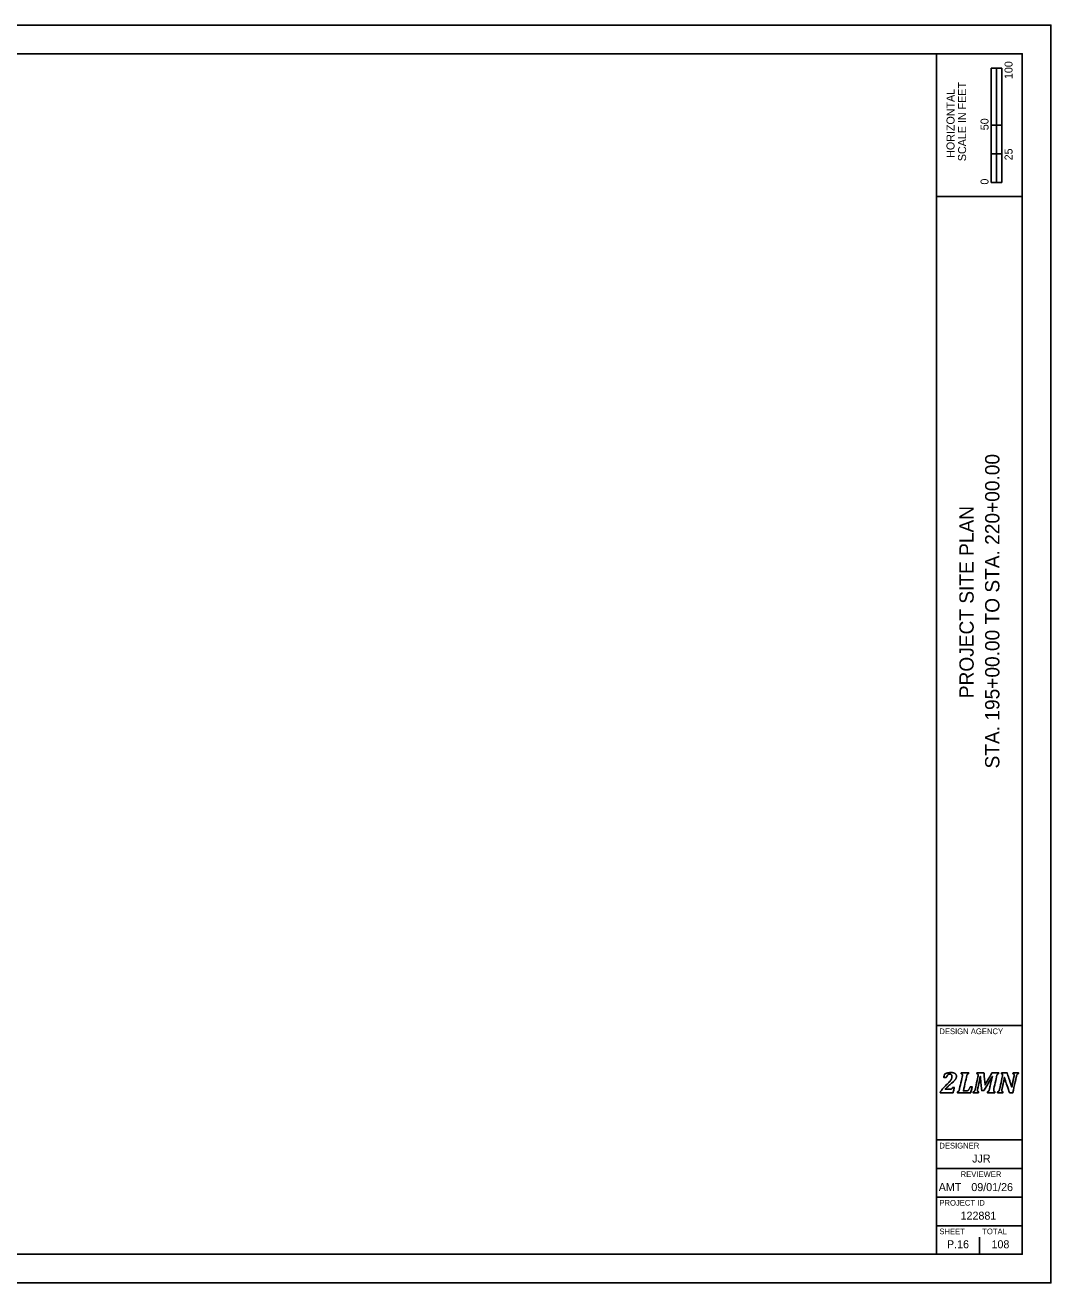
# Model space of a CAD drawing. Extents: x -1.9 to 34, y 0 to 22.
# Drawn here: x 16.06 to 34, y 0 to 22 of the extents above; entities that cross this region are included whole.
import ezdxf

# ---------------------------------------------------------------- set-up
doc = ezdxf.new("R2010")
doc.units = 0
for name, color, linetype in [('SH_Border', 7, 'Continuous'), ('SH_Cut_Line', 7, 'Continuous'), ('SH_Data', 7, 'Continuous')]:
    doc.layers.add(name, color=color, linetype=linetype)

msp = doc.modelspace()

# ---------------------------------------------------------------- linework, layer by layer
at = {"layer": 'SH_Border'}
for p, q in [((32, 0.5), (32, 21.5)), ((32, 19), (33.5, 19)), ((32, 4.5), (33.5, 4.5)), ((32, 2.5), (33.5, 2.5)), ((32, 2), (33.5, 2)), ((32, 1.5), (33.5, 1.5)), ((32, 1), (33.5, 1))]:
    msp.add_line(p, q, dxfattribs=at)
msp.add_lwpolyline([(1.5, 21.5), (33.5, 21.5), (33.5, 0.5), (1.5, 0.5)], close=True, dxfattribs=at)
at = {"layer": 'SH_Cut_Line'}
msp.add_lwpolyline([(0, 0), (34, 0), (34, 22), (0, 22)], close=True, dxfattribs=at)
at = {"layer": 'SH_Data'}
for p, q in [((32.957, 19.25), (32.957, 21.25)), ((33.144, 21.25), (32.957, 21.25)), ((32.957, 20.25), (32.957, 21.25)), ((32.957, 21.25), (33.05, 21.25)), ((33.05, 21.25), (33.051, 21.25)), ((33.051, 21.25), (33.051, 20.25)), ((33.144, 21.25), (33.144, 19.25)), ((33.051, 20.25), (32.957, 20.25)), ((33.143, 20.25), (33.05, 20.25)), ((33.05, 20.25), (33.05, 19.75)), ((33.143, 19.75), (33.143, 20.25)), ((33.05, 19.75), (32.957, 19.75)), ((32.957, 19.75), (32.957, 19.25)), ((33.05, 19.25), (33.05, 19.75)), ((33.05, 19.75), (33.143, 19.75)), ((33.144, 19.25), (32.957, 19.25)), ((32.957, 19.25), (33.05, 19.25)), ((32.75, 3.5), (32.75, 3.5)), ((32.375, 0.675), (32.375, 0.675)), ((32.75, 0.5), (32.75, 0.8))]:
    msp.add_line(p, q, dxfattribs=at)
for points in [[(32.237, 3.388), (32.246, 3.388), (32.253, 3.389), (32.258, 3.39), (32.263, 3.392), (32.267, 3.394), (32.27, 3.397), (32.273, 3.401), (32.277, 3.408), (32.281, 3.417), (32.281, 3.417), (32.312, 3.417), (32.312, 3.417), (32.312, 3.417), (32.29, 3.326), (32.29, 3.326), (32.29, 3.326), (32.066, 3.326), (32.066, 3.326), (32.066, 3.326), (32.069, 3.343), (32.069, 3.343), (32.078, 3.358), (32.091, 3.375), (32.106, 3.394), (32.122, 3.412), (32.144, 3.435), (32.172, 3.462), (32.197, 3.486), (32.217, 3.506), (32.23, 3.521), (32.243, 3.537), (32.253, 3.551), (32.259, 3.566), (32.266, 3.58), (32.269, 3.595), (32.269, 3.61), (32.269, 3.622), (32.266, 3.632), (32.26, 3.64), (32.253, 3.647), (32.245, 3.65), (32.234, 3.65), (32.22, 3.65), (32.208, 3.646), (32.198, 3.636), (32.188, 3.627), (32.18, 3.613), (32.172, 3.593), (32.172, 3.593), (32.126, 3.593), (32.126, 3.593), (32.126, 3.593), (32.14, 3.654), (32.14, 3.654), (32.166, 3.663), (32.188, 3.669), (32.205, 3.673), (32.223, 3.676), (32.24, 3.678), (32.258, 3.678), (32.278, 3.678), (32.295, 3.675), (32.309, 3.669), (32.322, 3.664), (32.332, 3.656), (32.339, 3.646), (32.345, 3.637), (32.348, 3.626), (32.348, 3.613), (32.348, 3.602), (32.346, 3.591), (32.342, 3.581), (32.339, 3.571), (32.333, 3.56), (32.324, 3.549), (32.315, 3.539), (32.304, 3.526), (32.289, 3.513), (32.275, 3.499), (32.254, 3.482), (32.228, 3.46), (32.216, 3.45), (32.202, 3.438), (32.188, 3.425), (32.174, 3.412), (32.162, 3.4), (32.154, 3.391), (32.154, 3.391), (32.153, 3.388), (32.153, 3.388), (32.153, 3.388), (32.237, 3.388), (32.237, 3.388)], [(32.237, 3.388), (32.237, 3.388), (32.153, 3.388), (32.153, 3.388), (32.153, 3.388), (32.154, 3.391), (32.154, 3.391), (32.162, 3.4), (32.174, 3.412), (32.188, 3.425), (32.202, 3.438), (32.216, 3.45), (32.228, 3.46), (32.254, 3.482), (32.275, 3.499), (32.289, 3.513), (32.304, 3.526), (32.315, 3.539), (32.324, 3.549), (32.333, 3.56), (32.339, 3.571), (32.342, 3.581), (32.346, 3.591), (32.348, 3.602), (32.348, 3.613), (32.348, 3.626), (32.345, 3.637), (32.339, 3.646), (32.332, 3.656), (32.322, 3.664), (32.309, 3.669), (32.295, 3.675), (32.278, 3.678), (32.258, 3.678), (32.24, 3.678), (32.223, 3.676), (32.205, 3.673), (32.188, 3.669), (32.166, 3.663), (32.14, 3.654), (32.14, 3.654), (32.126, 3.593), (32.126, 3.593), (32.126, 3.593), (32.172, 3.593), (32.172, 3.593), (32.18, 3.613), (32.188, 3.627), (32.198, 3.636), (32.208, 3.646), (32.22, 3.65), (32.234, 3.65), (32.245, 3.65), (32.253, 3.647), (32.26, 3.64), (32.266, 3.632), (32.269, 3.622), (32.269, 3.61), (32.269, 3.595), (32.266, 3.58), (32.259, 3.566), (32.253, 3.551), (32.243, 3.537), (32.23, 3.521), (32.217, 3.506), (32.197, 3.486), (32.172, 3.462), (32.144, 3.435), (32.122, 3.412), (32.106, 3.394), (32.091, 3.375), (32.078, 3.358), (32.069, 3.343), (32.069, 3.343), (32.066, 3.326), (32.066, 3.326), (32.066, 3.326), (32.29, 3.326), (32.29, 3.326), (32.29, 3.326), (32.312, 3.417), (32.312, 3.417), (32.312, 3.417), (32.281, 3.417), (32.281, 3.417), (32.277, 3.408), (32.273, 3.401), (32.27, 3.397), (32.267, 3.394), (32.263, 3.392), (32.258, 3.39), (32.253, 3.389), (32.246, 3.388), (32.237, 3.388)], [(32.518, 3.356), (32.527, 3.356), (32.533, 3.357), (32.538, 3.358), (32.542, 3.36), (32.546, 3.362), (32.55, 3.365), (32.554, 3.368), (32.558, 3.372), (32.562, 3.377), (32.567, 3.382), (32.571, 3.388), (32.576, 3.397), (32.58, 3.405), (32.585, 3.415), (32.589, 3.427), (32.589, 3.427), (32.624, 3.427), (32.624, 3.427), (32.624, 3.427), (32.598, 3.326), (32.598, 3.326), (32.598, 3.326), (32.365, 3.326), (32.365, 3.326), (32.365, 3.326), (32.369, 3.343), (32.369, 3.343), (32.376, 3.345), (32.381, 3.348), (32.385, 3.351), (32.389, 3.355), (32.392, 3.36), (32.395, 3.366), (32.398, 3.373), (32.4, 3.382), (32.403, 3.395), (32.403, 3.395), (32.449, 3.605), (32.449, 3.605), (32.452, 3.615), (32.453, 3.625), (32.453, 3.635), (32.453, 3.642), (32.451, 3.647), (32.448, 3.651), (32.444, 3.654), (32.439, 3.656), (32.432, 3.657), (32.432, 3.657), (32.435, 3.674), (32.435, 3.674), (32.435, 3.674), (32.563, 3.674), (32.563, 3.674), (32.563, 3.674), (32.559, 3.657), (32.559, 3.657), (32.552, 3.655), (32.547, 3.652), (32.543, 3.649), (32.539, 3.645), (32.536, 3.64), (32.533, 3.634), (32.531, 3.627), (32.528, 3.618), (32.525, 3.605), (32.525, 3.605), (32.47, 3.356), (32.47, 3.356), (32.47, 3.356), (32.518, 3.356), (32.518, 3.356)], [(32.518, 3.356), (32.518, 3.356), (32.47, 3.356), (32.47, 3.356), (32.47, 3.356), (32.525, 3.605), (32.525, 3.605), (32.528, 3.618), (32.531, 3.627), (32.533, 3.634), (32.536, 3.64), (32.539, 3.645), (32.543, 3.649), (32.547, 3.652), (32.552, 3.655), (32.559, 3.657), (32.559, 3.657), (32.563, 3.674), (32.563, 3.674), (32.563, 3.674), (32.435, 3.674), (32.435, 3.674), (32.435, 3.674), (32.432, 3.657), (32.432, 3.657), (32.439, 3.656), (32.444, 3.654), (32.448, 3.651), (32.451, 3.647), (32.453, 3.642), (32.453, 3.635), (32.453, 3.625), (32.452, 3.615), (32.449, 3.605), (32.449, 3.605), (32.403, 3.395), (32.403, 3.395), (32.4, 3.382), (32.398, 3.373), (32.395, 3.366), (32.392, 3.36), (32.389, 3.355), (32.385, 3.351), (32.381, 3.348), (32.376, 3.345), (32.369, 3.343), (32.369, 3.343), (32.365, 3.326), (32.365, 3.326), (32.365, 3.326), (32.598, 3.326), (32.598, 3.326), (32.598, 3.326), (32.624, 3.427), (32.624, 3.427), (32.624, 3.427), (32.589, 3.427), (32.589, 3.427), (32.585, 3.415), (32.58, 3.405), (32.576, 3.397), (32.571, 3.388), (32.567, 3.382), (32.562, 3.377), (32.558, 3.372), (32.554, 3.368), (32.55, 3.365), (32.546, 3.362), (32.542, 3.36), (32.538, 3.358), (32.533, 3.357), (32.527, 3.356), (32.518, 3.356)], [(32.829, 3.674), (32.829, 3.674), (32.849, 3.461), (32.849, 3.461), (32.849, 3.461), (32.969, 3.674), (32.969, 3.674), (32.969, 3.674), (33.087, 3.674), (33.087, 3.674), (33.087, 3.674), (33.084, 3.657), (33.084, 3.657), (33.077, 3.655), (33.071, 3.652), (33.067, 3.649), (33.064, 3.645), (33.06, 3.64), (33.058, 3.634), (33.055, 3.627), (33.052, 3.618), (33.05, 3.605), (33.05, 3.605), (33.003, 3.395), (33.003, 3.395), (33.002, 3.39), (33.002, 3.387), (33.001, 3.384), (33.001, 3.382), (33.001, 3.379), (33, 3.376), (33, 3.373), (33, 3.369), (33, 3.365), (33, 3.358), (33.002, 3.353), (33.005, 3.349), (33.008, 3.346), (33.014, 3.344), (33.021, 3.343), (33.021, 3.343), (33.018, 3.326), (33.018, 3.326), (33.018, 3.326), (32.89, 3.326), (32.89, 3.326), (32.89, 3.326), (32.893, 3.343), (32.893, 3.343), (32.9, 3.345), (32.906, 3.348), (32.91, 3.351), (32.914, 3.355), (32.917, 3.36), (32.919, 3.366), (32.922, 3.373), (32.925, 3.382), (32.928, 3.395), (32.928, 3.395), (32.951, 3.502), (32.951, 3.502), (32.954, 3.513), (32.957, 3.529), (32.962, 3.548), (32.967, 3.568), (32.972, 3.588), (32.978, 3.609), (32.978, 3.609), (32.973, 3.609), (32.973, 3.609), (32.965, 3.594), (32.957, 3.579), (32.948, 3.563), (32.948, 3.563), (32.833, 3.364), (32.833, 3.364), (32.833, 3.364), (32.792, 3.364), (32.792, 3.364), (32.792, 3.364), (32.775, 3.518), (32.775, 3.518), (32.773, 3.537), (32.772, 3.554), (32.77, 3.569), (32.769, 3.583), (32.768, 3.597), (32.768, 3.611), (32.768, 3.611), (32.764, 3.611), (32.764, 3.611), (32.761, 3.596), (32.758, 3.578), (32.755, 3.558), (32.751, 3.538), (32.747, 3.521), (32.744, 3.507), (32.744, 3.507), (32.72, 3.395), (32.72, 3.395), (32.719, 3.39), (32.718, 3.387), (32.718, 3.384), (32.717, 3.382), (32.717, 3.379), (32.717, 3.376), (32.717, 3.373), (32.716, 3.369), (32.716, 3.365), (32.716, 3.358), (32.718, 3.353), (32.721, 3.349), (32.725, 3.346), (32.73, 3.344), (32.738, 3.343), (32.738, 3.343), (32.734, 3.326), (32.734, 3.326), (32.734, 3.326), (32.641, 3.326), (32.641, 3.326), (32.641, 3.326), (32.644, 3.343), (32.644, 3.343), (32.651, 3.345), (32.657, 3.348), (32.661, 3.351), (32.665, 3.355), (32.668, 3.36), (32.67, 3.366), (32.673, 3.373), (32.676, 3.382), (32.679, 3.395), (32.679, 3.395), (32.725, 3.605), (32.725, 3.605), (32.727, 3.615), (32.728, 3.625), (32.728, 3.635), (32.728, 3.642), (32.727, 3.647), (32.723, 3.651), (32.72, 3.654), (32.715, 3.656), (32.707, 3.657), (32.707, 3.657), (32.711, 3.674), (32.711, 3.674), (32.711, 3.674), (32.829, 3.674), (32.829, 3.674)], [(32.829, 3.674), (32.829, 3.674), (32.711, 3.674), (32.711, 3.674), (32.711, 3.674), (32.707, 3.657), (32.707, 3.657), (32.715, 3.656), (32.72, 3.654), (32.723, 3.651), (32.727, 3.647), (32.728, 3.642), (32.728, 3.635), (32.728, 3.625), (32.727, 3.615), (32.725, 3.605), (32.725, 3.605), (32.679, 3.395), (32.679, 3.395), (32.676, 3.382), (32.673, 3.373), (32.67, 3.366), (32.668, 3.36), (32.665, 3.355), (32.661, 3.351), (32.657, 3.348), (32.651, 3.345), (32.644, 3.343), (32.644, 3.343), (32.641, 3.326), (32.641, 3.326), (32.641, 3.326), (32.734, 3.326), (32.734, 3.326), (32.734, 3.326), (32.738, 3.343), (32.738, 3.343), (32.73, 3.344), (32.725, 3.346), (32.721, 3.349), (32.718, 3.353), (32.716, 3.358), (32.716, 3.365), (32.716, 3.369), (32.717, 3.373), (32.717, 3.376), (32.717, 3.379), (32.717, 3.382), (32.718, 3.384), (32.718, 3.387), (32.719, 3.39), (32.72, 3.395), (32.72, 3.395), (32.744, 3.507), (32.744, 3.507), (32.747, 3.521), (32.751, 3.538), (32.755, 3.558), (32.758, 3.578), (32.761, 3.596), (32.764, 3.611), (32.764, 3.611), (32.768, 3.611), (32.768, 3.611), (32.768, 3.597), (32.769, 3.583), (32.77, 3.569), (32.772, 3.554), (32.773, 3.537), (32.775, 3.518), (32.775, 3.518), (32.792, 3.364), (32.792, 3.364), (32.792, 3.364), (32.833, 3.364), (32.833, 3.364), (32.833, 3.364), (32.948, 3.563), (32.948, 3.563), (32.957, 3.579), (32.965, 3.594), (32.973, 3.609), (32.973, 3.609), (32.978, 3.609), (32.978, 3.609), (32.972, 3.588), (32.967, 3.568), (32.962, 3.548), (32.957, 3.529), (32.954, 3.513), (32.951, 3.502), (32.951, 3.502), (32.928, 3.395), (32.928, 3.395), (32.925, 3.382), (32.922, 3.373), (32.919, 3.366), (32.917, 3.36), (32.914, 3.355), (32.91, 3.351), (32.906, 3.348), (32.9, 3.345), (32.893, 3.343), (32.893, 3.343), (32.89, 3.326), (32.89, 3.326), (32.89, 3.326), (33.018, 3.326), (33.018, 3.326), (33.018, 3.326), (33.021, 3.343), (33.021, 3.343), (33.014, 3.344), (33.008, 3.346), (33.005, 3.349), (33.002, 3.353), (33, 3.358), (33, 3.365), (33, 3.369), (33, 3.373), (33, 3.376), (33.001, 3.379), (33.001, 3.382), (33.001, 3.384), (33.002, 3.387), (33.002, 3.39), (33.003, 3.395), (33.003, 3.395), (33.05, 3.605), (33.05, 3.605), (33.052, 3.618), (33.055, 3.627), (33.058, 3.634), (33.06, 3.64), (33.064, 3.645), (33.067, 3.649), (33.071, 3.652), (33.077, 3.655), (33.084, 3.657), (33.084, 3.657), (33.087, 3.674), (33.087, 3.674), (33.087, 3.674), (32.969, 3.674), (32.969, 3.674), (32.969, 3.674), (32.849, 3.461), (32.849, 3.461), (32.849, 3.461), (32.829, 3.674), (32.829, 3.674)], [(33.137, 3.674), (33.137, 3.674), (33.234, 3.674), (33.234, 3.674), (33.234, 3.674), (33.283, 3.53), (33.283, 3.53), (33.296, 3.49), (33.307, 3.456), (33.315, 3.426), (33.315, 3.426), (33.318, 3.426), (33.318, 3.426), (33.323, 3.455), (33.329, 3.488), (33.337, 3.523), (33.337, 3.523), (33.355, 3.605), (33.355, 3.605), (33.357, 3.615), (33.358, 3.625), (33.358, 3.635), (33.358, 3.642), (33.357, 3.647), (33.353, 3.651), (33.35, 3.654), (33.345, 3.656), (33.337, 3.657), (33.337, 3.657), (33.341, 3.674), (33.341, 3.674), (33.341, 3.674), (33.434, 3.674), (33.434, 3.674), (33.434, 3.674), (33.431, 3.657), (33.431, 3.657), (33.424, 3.655), (33.418, 3.652), (33.414, 3.649), (33.41, 3.645), (33.407, 3.64), (33.405, 3.634), (33.402, 3.627), (33.399, 3.618), (33.396, 3.605), (33.396, 3.605), (33.335, 3.326), (33.335, 3.326), (33.335, 3.326), (33.277, 3.326), (33.277, 3.326), (33.277, 3.326), (33.216, 3.504), (33.216, 3.504), (33.211, 3.518), (33.207, 3.531), (33.204, 3.543), (33.2, 3.556), (33.195, 3.571), (33.19, 3.59), (33.19, 3.59), (33.186, 3.59), (33.186, 3.59), (33.185, 3.579), (33.182, 3.563), (33.179, 3.543), (33.175, 3.523), (33.17, 3.501), (33.165, 3.478), (33.165, 3.478), (33.147, 3.395), (33.147, 3.395), (33.146, 3.39), (33.145, 3.387), (33.145, 3.384), (33.144, 3.382), (33.144, 3.379), (33.144, 3.376), (33.143, 3.373), (33.143, 3.369), (33.143, 3.365), (33.143, 3.358), (33.145, 3.353), (33.148, 3.349), (33.152, 3.346), (33.157, 3.344), (33.164, 3.343), (33.164, 3.343), (33.161, 3.326), (33.161, 3.326), (33.161, 3.326), (33.067, 3.326), (33.067, 3.326), (33.067, 3.326), (33.071, 3.343), (33.071, 3.343), (33.078, 3.345), (33.083, 3.348), (33.087, 3.351), (33.091, 3.355), (33.094, 3.36), (33.097, 3.366), (33.1, 3.373), (33.102, 3.382), (33.105, 3.395), (33.105, 3.395), (33.151, 3.605), (33.151, 3.605), (33.154, 3.615), (33.155, 3.625), (33.155, 3.635), (33.155, 3.642), (33.153, 3.647), (33.15, 3.651), (33.146, 3.654), (33.141, 3.656), (33.134, 3.657), (33.134, 3.657), (33.137, 3.674), (33.137, 3.674)], [(33.137, 3.674), (33.137, 3.674), (33.134, 3.657), (33.134, 3.657), (33.141, 3.656), (33.146, 3.654), (33.15, 3.651), (33.153, 3.647), (33.155, 3.642), (33.155, 3.635), (33.155, 3.625), (33.154, 3.615), (33.151, 3.605), (33.151, 3.605), (33.105, 3.395), (33.105, 3.395), (33.102, 3.382), (33.1, 3.373), (33.097, 3.366), (33.094, 3.36), (33.091, 3.355), (33.087, 3.351), (33.083, 3.348), (33.078, 3.345), (33.071, 3.343), (33.071, 3.343), (33.067, 3.326), (33.067, 3.326), (33.067, 3.326), (33.161, 3.326), (33.161, 3.326), (33.161, 3.326), (33.164, 3.343), (33.164, 3.343), (33.157, 3.344), (33.152, 3.346), (33.148, 3.349), (33.145, 3.353), (33.143, 3.358), (33.143, 3.365), (33.143, 3.369), (33.143, 3.373), (33.144, 3.376), (33.144, 3.379), (33.144, 3.382), (33.145, 3.384), (33.145, 3.387), (33.146, 3.39), (33.147, 3.395), (33.147, 3.395), (33.165, 3.478), (33.165, 3.478), (33.17, 3.501), (33.175, 3.523), (33.179, 3.543), (33.182, 3.563), (33.185, 3.579), (33.186, 3.59), (33.186, 3.59), (33.19, 3.59), (33.19, 3.59), (33.195, 3.571), (33.2, 3.556), (33.204, 3.543), (33.207, 3.531), (33.211, 3.518), (33.216, 3.504), (33.216, 3.504), (33.277, 3.326), (33.277, 3.326), (33.277, 3.326), (33.335, 3.326), (33.335, 3.326), (33.335, 3.326), (33.396, 3.605), (33.396, 3.605), (33.399, 3.618), (33.402, 3.627), (33.405, 3.634), (33.407, 3.64), (33.41, 3.645), (33.414, 3.649), (33.418, 3.652), (33.424, 3.655), (33.431, 3.657), (33.431, 3.657), (33.434, 3.674), (33.434, 3.674), (33.434, 3.674), (33.341, 3.674), (33.341, 3.674), (33.341, 3.674), (33.337, 3.657), (33.337, 3.657), (33.345, 3.656), (33.35, 3.654), (33.353, 3.651), (33.357, 3.647), (33.358, 3.642), (33.358, 3.635), (33.358, 3.625), (33.357, 3.615), (33.355, 3.605), (33.355, 3.605), (33.337, 3.523), (33.337, 3.523), (33.329, 3.488), (33.323, 3.455), (33.318, 3.426), (33.318, 3.426), (33.315, 3.426), (33.315, 3.426), (33.307, 3.456), (33.296, 3.49), (33.283, 3.53), (33.283, 3.53), (33.234, 3.674), (33.234, 3.674), (33.234, 3.674), (33.137, 3.674), (33.137, 3.674)]]:
    msp.add_open_spline(points, degree=3, dxfattribs=at)

# ---------------------------------------------------------------- texts
for s, height, p in [('100', 0.14, (33.33, 21.057)), ('SCALE IN FEET', 0.14, (32.517, 19.621)), ('HORIZONTAL', 0.14, (32.315, 19.679)), ('50', 0.14, (32.91, 20.162)), ('25', 0.14, (33.33, 19.635)), ('0', 0.14, (32.91, 19.211)), ('STA. 195+00.00 TO STA. 220+00.00', 0.25, (33.1, 8.998)), ('PROJECT SITE PLAN', 0.25, (32.65, 10.227))]:
    msp.add_text(s, height=height, rotation=90, dxfattribs=at).set_placement(p)
for s, height, p in [('DESIGN AGENCY', 0.1, (32.05, 4.35)), ('DESIGNER', 0.1, (32.05, 2.35)), ('JJR', 0.14, (32.624, 2.105)), ('REVIEWER', 0.1, (32.422, 1.85)), ('AMT', 0.14, (32.039, 1.605)), ('09/01/26', 0.14, (32.609, 1.605)), ('PROJECT ID', 0.1, (32.05, 1.35)), ('122881', 0.14, (32.421, 1.105)), ('SHEET', 0.1, (32.05, 0.85)), ('TOTAL', 0.1, (32.8, 0.85)), ('P.16', 0.14, (32.183, 0.605)), ('108', 0.14, (32.962, 0.605))]:
    msp.add_text(s, height=height, dxfattribs=at).set_placement(p)

doc.saveas('drawing.dxf')
